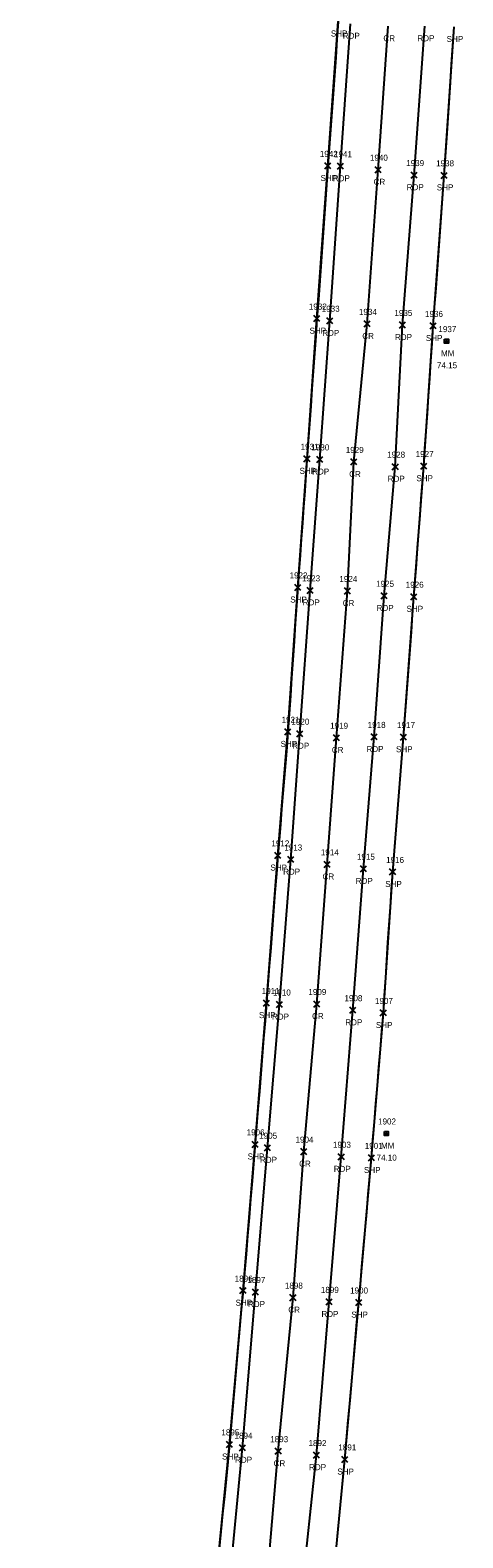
# Model space of a CAD drawing. Extents: x 1688195 to 1692013, y 424605 to 441234.
# Drawn here: x 1690497 to 1690640, y 435648 to 436148 of the extents above; entities that cross this region are included whole.
import ezdxf

# ---------------------------------------------------------------- set-up
doc = ezdxf.new("R2010")
doc.units = 0
for name, color, linetype in [('LSOGP', 7, 'Continuous'), ('P_A', 7, 'Continuous'), ('P_I', 7, 'Continuous'), ('P_TIC', 7, 'Continuous'), ('PET', 7, 'Continuous'), ('PRC', 7, 'Continuous'), ('PSP', 7, 'Continuous'), ('S_A', 7, 'Continuous'), ('S_C', 7, 'Continuous'), ('S_I', 7, 'Continuous'), ('SRM', 7, 'Continuous')]:
    doc.layers.add(name, color=color, linetype=linetype)

msp = doc.modelspace()

# ---------------------------------------------------------------- linework, layer by layer
at = {"layer": 'LSOGP'}
for points in [[(1690599.5, 436156.87), (1690598.67, 436145.19), (1690598.25, 436139.19), (1690597.82, 436133.2), (1690597.39, 436127.2), (1690596.96, 436121.21), (1690596.53, 436115.22), (1690596.11, 436109.22), (1690595.68, 436103.23), (1690595.22, 436096.9), (1690594.77, 436090.56), (1690594.31, 436084.23), (1690593.85, 436077.89), (1690593.4, 436071.56), (1690592.94, 436065.22), (1690592.49, 436058.89), (1690592.03, 436052.55), (1690591.62, 436046.74), (1690591.2, 436040.93), (1690590.79, 436035.11), (1690590.38, 436029.3), (1690589.97, 436023.48), (1690589.56, 436017.67), (1690589.14, 436011.86), (1690588.35, 436000.7), (1690587.96, 435995.36), (1690587.57, 435990.02), (1690587.19, 435984.68), (1690586.8, 435979.34), (1690586.41, 435974.01), (1690586.03, 435968.67), (1690585.64, 435963.33), (1690585.24, 435957.34), (1690584.84, 435951.35), (1690584.43, 435945.36), (1690584.03, 435939.37), (1690583.63, 435933.39), (1690583.23, 435927.4), (1690582.82, 435921.41), (1690582.42, 435915.42), (1690582, 435910.29), (1690581.58, 435905.17), (1690581.16, 435900.04), (1690580.74, 435894.91), (1690580.32, 435889.78), (1690579.9, 435884.65), (1690579.48, 435879.52), (1690579.05, 435874.39), (1690578.58, 435868.27), (1690578.11, 435862.15), (1690577.64, 435856.03), (1690577.17, 435849.91), (1690576.69, 435843.79), (1690576.22, 435837.66), (1690575.75, 435831.54), (1690575.28, 435825.42), (1690574.81, 435819.56), (1690574.34, 435813.69), (1690573.88, 435807.83), (1690573.41, 435801.97), (1690572.94, 435796.1), (1690572.47, 435790.24), (1690570.53, 435766.38), (1690570.03, 435760.31), (1690569.52, 435754.25), (1690569.02, 435748.18), (1690568.52, 435742.11), (1690568.01, 435736.05), (1690567.51, 435729.98), (1690566.95, 435723.6), (1690566.39, 435717.22), (1690565.84, 435710.84), (1690565.28, 435704.46), (1690564.72, 435698.08), (1690564.16, 435691.7), (1690563.6, 435685.31), (1690563.05, 435678.93), (1690562.47, 435673.17), (1690561.9, 435667.4), (1690561.33, 435661.63), (1690560.76, 435655.87), (1690560.18, 435650.1), (1690559.61, 435644.34)], [(1690598.48, 435644.97), (1690599.03, 435650.77), (1690599.59, 435656.56), (1690600.14, 435662.36), (1690600.7, 435668.15), (1690601.25, 435673.95), (1690601.83, 435680.46), (1690602.41, 435686.97), (1690602.99, 435693.48), (1690603.57, 435699.99), (1690604.15, 435706.5), (1690604.72, 435713.01), (1690605.3, 435719.52), (1690605.88, 435726.03), (1690606.41, 435732.03), (1690606.93, 435738.03), (1690607.46, 435744.03), (1690607.98, 435750.02), (1690608.51, 435756.02), (1690609.03, 435762.02), (1690609.56, 435768.02), (1690610.09, 435774.02), (1690610.58, 435780.03), (1690611.07, 435786.04), (1690611.57, 435792.06), (1690612.06, 435798.07), (1690612.55, 435804.09), (1690613.05, 435810.1), (1690613.54, 435816.12), (1690614.04, 435822.13), (1690614.42, 435827.98), (1690614.81, 435833.83), (1690615.2, 435839.68), (1690615.58, 435845.52), (1690615.97, 435851.37), (1690616.36, 435857.22), (1690616.74, 435863.07), (1690617.58, 435874.51), (1690618.02, 435880.1), (1690618.47, 435885.69), (1690618.92, 435891.28), (1690619.37, 435896.87), (1690619.81, 435902.46), (1690620.26, 435908.05), (1690620.71, 435913.65), (1690621.14, 435919.47), (1690621.58, 435925.3), (1690622.02, 435931.12), (1690622.45, 435936.95), (1690622.89, 435942.78), (1690623.32, 435948.6), (1690623.76, 435954.43), (1690624.19, 435960.25), (1690624.6, 435965.67), (1690625.01, 435971.09), (1690625.41, 435976.51), (1690625.82, 435981.93), (1690626.23, 435987.35), (1690626.63, 435992.77), (1690627.04, 435998.19), (1690627.45, 436003.61), (1690627.84, 436009.42), (1690628.23, 436015.24), (1690628.63, 436021.05), (1690629.02, 436026.86), (1690629.42, 436032.68), (1690629.81, 436038.49), (1690630.21, 436044.31), (1690630.6, 436050.12), (1690631.05, 436056.37), (1690631.51, 436062.62), (1690631.96, 436068.86), (1690632.41, 436075.11), (1690632.87, 436081.36), (1690633.32, 436087.61), (1690633.77, 436093.86), (1690634.23, 436100.1), (1690634.63, 436106.26), (1690635.04, 436112.42), (1690636.27, 436130.89), (1690636.68, 436137.05), (1690637.08, 436143.21), (1690637.49, 436149.36)]]:
    msp.add_lwpolyline(points, dxfattribs=at)
at = {"layer": 'P_TIC'}
for points in [[(1690594.68, 436102.23), (1690596.68, 436104.23)], [(1690596.68, 436102.23), (1690594.68, 436104.23)], [(1690598.8, 436102.13), (1690600.8, 436104.13)], [(1690600.8, 436102.13), (1690598.8, 436104.13)], [(1690611.37, 436100.96), (1690613.37, 436102.96)], [(1690613.37, 436100.96), (1690611.37, 436102.96)], [(1690623.3, 436099.17), (1690625.3, 436101.17)], [(1690625.3, 436099.17), (1690623.3, 436101.17)], [(1690633.23, 436099.1), (1690635.23, 436101.1)], [(1690635.23, 436099.1), (1690633.23, 436101.1)], [(1690591.03, 436051.55), (1690593.03, 436053.55)], [(1690593.03, 436051.55), (1690591.03, 436053.55)], [(1690595.29, 436050.83), (1690597.29, 436052.83)], [(1690597.29, 436050.83), (1690595.29, 436052.83)], [(1690607.63, 436049.8), (1690609.63, 436051.8)], [(1690609.63, 436049.8), (1690607.63, 436051.8)], [(1690619.4, 436049.44), (1690621.4, 436051.44)], [(1690621.4, 436049.44), (1690619.4, 436051.44)], [(1690629.6, 436049.12), (1690631.6, 436051.12)], [(1690631.6, 436049.12), (1690629.6, 436051.12)], [(1690587.73, 436005.04), (1690589.73, 436007.04)], [(1690589.73, 436005.04), (1690587.73, 436007.04)], [(1690591.94, 436004.81), (1690593.94, 436006.81)], [(1690593.94, 436004.81), (1690591.94, 436006.81)], [(1690603.28, 436003.98), (1690605.28, 436005.98)], [(1690605.28, 436003.98), (1690603.28, 436005.98)], [(1690617.01, 436002.42), (1690619.01, 436004.42)], [(1690619.01, 436002.42), (1690617.01, 436004.42)], [(1690626.45, 436002.61), (1690628.45, 436004.61)], [(1690628.45, 436002.61), (1690626.45, 436004.61)], [(1690584.64, 435962.33), (1690586.64, 435964.33)], [(1690586.64, 435962.33), (1690584.64, 435964.33)], [(1690588.82, 435961.37), (1690590.82, 435963.37)], [(1690590.82, 435961.37), (1690588.82, 435963.37)], [(1690601.14, 435961.16), (1690603.14, 435963.16)], [(1690603.14, 435961.16), (1690601.14, 435963.16)], [(1690613.33, 435959.55), (1690615.33, 435961.55)], [(1690615.33, 435959.55), (1690613.33, 435961.55)], [(1690623.19, 435959.25), (1690625.19, 435961.25)], [(1690625.19, 435959.25), (1690623.19, 435961.25)], [(1690581.42, 435914.42), (1690583.42, 435916.42)], [(1690583.42, 435914.42), (1690581.42, 435916.42)], [(1690585.33, 435913.81), (1690587.33, 435915.81)], [(1690587.33, 435913.81), (1690585.33, 435915.81)], [(1690597.53, 435912.43), (1690599.53, 435914.43)], [(1690599.53, 435912.43), (1690597.53, 435914.43)], [(1690609.97, 435912.73), (1690611.97, 435914.73)], [(1690611.97, 435912.73), (1690609.97, 435914.73)], [(1690619.71, 435912.65), (1690621.71, 435914.65)], [(1690621.71, 435912.65), (1690619.71, 435914.65)], [(1690578.05, 435873.39), (1690580.05, 435875.39)], [(1690580.05, 435873.39), (1690578.05, 435875.39)], [(1690582.32, 435872.03), (1690584.32, 435874.03)], [(1690584.32, 435872.03), (1690582.32, 435874.03)], [(1690594.45, 435870.42), (1690596.45, 435872.42)], [(1690596.45, 435870.42), (1690594.45, 435872.42)], [(1690606.41, 435868.96), (1690608.41, 435870.96)], [(1690608.41, 435868.96), (1690606.41, 435870.96)], [(1690616.13, 435867.92), (1690618.13, 435869.92)], [(1690618.13, 435867.92), (1690616.13, 435869.92)], [(1690574.28, 435824.42), (1690576.28, 435826.42)], [(1690576.28, 435824.42), (1690574.28, 435826.42)], [(1690578.63, 435823.92), (1690580.63, 435825.92)], [(1690580.63, 435823.92), (1690578.63, 435825.92)], [(1690590.96, 435824.1), (1690592.96, 435826.1)], [(1690592.96, 435824.1), (1690590.96, 435826.1)], [(1690602.92, 435822.04), (1690604.92, 435824.04)], [(1690604.92, 435822.04), (1690602.92, 435824.04)], [(1690613.04, 435821.13), (1690615.04, 435823.13)], [(1690615.04, 435821.13), (1690613.04, 435823.13)], [(1690570.54, 435777.51), (1690572.54, 435779.51)], [(1690572.54, 435777.51), (1690570.54, 435779.51)], [(1690574.66, 435776.41), (1690576.66, 435778.41)], [(1690576.66, 435776.41), (1690574.66, 435778.41)], [(1690586.69, 435775.1), (1690588.69, 435777.1)], [(1690588.69, 435775.1), (1690586.69, 435777.1)], [(1690599.11, 435773.4), (1690601.11, 435775.4)], [(1690601.11, 435773.4), (1690599.11, 435775.4)], [(1690609.09, 435773.02), (1690611.09, 435775.02)], [(1690611.09, 435773.02), (1690609.09, 435775.02)], [(1690566.51, 435728.98), (1690568.51, 435730.98)], [(1690568.51, 435728.98), (1690566.51, 435730.98)], [(1690570.67, 435728.52), (1690572.67, 435730.52)], [(1690572.67, 435728.52), (1690570.67, 435730.52)], [(1690583.09, 435726.65), (1690585.09, 435728.65)], [(1690585.09, 435726.65), (1690583.09, 435728.65)], [(1690595.03, 435725.24), (1690597.03, 435727.24)], [(1690597.03, 435725.24), (1690595.03, 435727.24)], [(1690604.88, 435725.03), (1690606.88, 435727.03)], [(1690606.88, 435725.03), (1690604.88, 435727.03)], [(1690562.05, 435677.93), (1690564.05, 435679.93)], [(1690564.05, 435677.93), (1690562.05, 435679.93)], [(1690566.39, 435676.85), (1690568.39, 435678.85)], [(1690568.39, 435676.85), (1690566.39, 435678.85)], [(1690578.22, 435675.69), (1690580.22, 435677.69)], [(1690580.22, 435675.69), (1690578.22, 435677.69)], [(1690590.92, 435674.4), (1690592.92, 435676.4)], [(1690592.92, 435674.4), (1690590.92, 435676.4)], [(1690600.25, 435672.95), (1690602.25, 435674.95)], [(1690602.25, 435672.95), (1690600.25, 435674.95)]]:
    msp.add_lwpolyline(points, dxfattribs=at)
at = {"layer": 'PET'}
for points in [[(1690501.19, 435117.33), (1690507.41, 435161.22), (1690513.67, 435205.88), (1690519.63, 435254.45), (1690525.65, 435299.76), (1690531.81, 435349.11), (1690537.74, 435397.15), (1690543.58, 435444.91), (1690548.36, 435492.43), (1690553.28, 435538.48), (1690558.17, 435585.77), (1690562.99, 435632.63), (1690567.39, 435677.85), (1690571.67, 435729.52), (1690575.66, 435777.41), (1690579.63, 435824.92), (1690583.32, 435873.03), (1690586.33, 435914.81), (1690589.82, 435962.37), (1690592.94, 436005.81), (1690596.29, 436051.83), (1690599.8, 436103.13), (1690603.11, 436150.42)], [(1690525.5, 435112.81), (1690531.76, 435157.71), (1690537.76, 435203.09), (1690544.15, 435250.79), (1690550.01, 435296.11), (1690556.39, 435345.44), (1690562.09, 435393.57), (1690567.56, 435441.2), (1690572.36, 435489.16), (1690577.37, 435534.18), (1690582.68, 435583.71), (1690586.85, 435628.48), (1690591.92, 435675.4), (1690596.03, 435726.24), (1690600.11, 435774.4), (1690603.92, 435823.04), (1690607.41, 435869.96), (1690610.97, 435913.73), (1690614.33, 435960.55), (1690618.01, 436003.42), (1690620.4, 436050.44), (1690624.3, 436100.17), (1690627.83, 436149.61)]]:
    msp.add_lwpolyline(points, dxfattribs=at)
at = {"layer": 'PRC'}
msp.add_lwpolyline([(1690513.41, 435116), (1690519.53, 435159.11), (1690525.48, 435205.46), (1690532.12, 435252.74), (1690538.16, 435298.47), (1690544.06, 435346.3), (1690550.13, 435396.05), (1690555.89, 435442.49), (1690560.85, 435491.32), (1690565.49, 435535.56), (1690570.86, 435584.47), (1690575.18, 435630.07), (1690579.22, 435676.69), (1690584.09, 435727.65), (1690587.69, 435776.1), (1690591.96, 435825.1), (1690595.45, 435871.42), (1690598.53, 435913.43), (1690602.14, 435962.16), (1690604.28, 436004.98), (1690608.63, 436050.8), (1690612.37, 436101.96), (1690615.61, 436149.6)], dxfattribs=at)
at = {"layer": 'PSP'}
for points in [[(1690496.95, 435118.58), (1690503.25, 435162.44), (1690509.51, 435207.35), (1690515.85, 435255.4), (1690521.64, 435301.74), (1690527.7, 435348.89), (1690533.61, 435398.55), (1690540.53, 435445.33), (1690544.23, 435493.64), (1690548.91, 435538.68), (1690553.85, 435586.59), (1690558.47, 435632.8), (1690563.05, 435678.93), (1690567.51, 435729.98), (1690571.54, 435778.51), (1690575.28, 435825.42), (1690579.05, 435874.39), (1690582.42, 435915.42), (1690585.64, 435963.33), (1690588.73, 436006.04), (1690592.03, 436052.55), (1690595.68, 436103.23), (1690599.1, 436151.18)], [(1690535.08, 435111.69), (1690541.36, 435156.27), (1690547.71, 435202), (1690554, 435247.6), (1690559.59, 435294.31), (1690565.75, 435344.26), (1690571.6, 435392), (1690577.62, 435439.9), (1690582.42, 435487.22), (1690587.27, 435533.5), (1690591.92, 435582.16), (1690596.81, 435627.59), (1690601.25, 435673.95), (1690605.88, 435726.03), (1690610.09, 435774.02), (1690614.04, 435822.13), (1690617.13, 435868.92), (1690620.71, 435913.65), (1690624.19, 435960.25), (1690627.45, 436003.61), (1690630.6, 436050.12), (1690634.23, 436100.1), (1690637.49, 436149.36)]]:
    msp.add_lwpolyline(points, dxfattribs=at)
at = {"layer": 'SRM'}
for points in [[(1690634.35, 436045.7), (1690635.6, 436045.7), (1690635.6, 436044.45), (1690634.35, 436044.45)], [(1690614.44, 435782.74), (1690615.69, 435782.74), (1690615.69, 435781.49), (1690614.44, 435781.49)]]:
    msp.add_lwpolyline(points, close=True, dxfattribs=at)
for centre in [(1690634.98, 436045.07), (1690615.06, 435782.12)]:
    msp.add_circle(centre, 0.0833, dxfattribs=at)

# ---------------------------------------------------------------- texts
at = {"layer": 'P_A'}
for s, p in [('SHP', (1690596.64, 436146.18)), ('RDP', (1690600.59, 436145.42)), ('CR', (1690614.04, 436144.6)), ('RDP', (1690625.32, 436144.61)), ('SHP', (1690635.03, 436144.36)), ('SHP', (1690593.21, 436098.23)), ('RDP', (1690597.29, 436098.13)), ('CR', (1690610.81, 436096.96)), ('RDP', (1690621.79, 436095.17)), ('SHP', (1690631.76, 436095.1)), ('SHP', (1690589.56, 436047.55)), ('RDP', (1690593.78, 436046.83)), ('CR', (1690607.06, 436045.8)), ('RDP', (1690617.89, 436045.44)), ('SHP', (1690628.14, 436045.12)), ('SHP', (1690586.27, 436001.04)), ('RDP', (1690590.43, 436000.81)), ('CR', (1690602.71, 435999.98)), ('RDP', (1690615.49, 435998.42)), ('SHP', (1690624.98, 435998.61)), ('SHP', (1690583.18, 435958.33)), ('RDP', (1690587.31, 435957.37)), ('CR', (1690600.57, 435957.16)), ('RDP', (1690611.81, 435955.55)), ('SHP', (1690621.73, 435955.25)), ('SHP', (1690579.96, 435910.42)), ('RDP', (1690583.82, 435909.81)), ('CR', (1690596.96, 435908.43)), ('RDP', (1690608.46, 435908.73)), ('SHP', (1690618.24, 435908.65)), ('SHP', (1690576.59, 435869.39)), ('RDP', (1690580.8, 435868.03)), ('CR', (1690593.88, 435866.42)), ('RDP', (1690604.89, 435864.96)), ('SHP', (1690614.66, 435863.92)), ('SHP', (1690572.81, 435820.42)), ('RDP', (1690577.12, 435819.92)), ('CR', (1690590.4, 435820.1)), ('RDP', (1690601.41, 435818.04)), ('SHP', (1690611.57, 435817.13)), ('SHP', (1690569.07, 435773.51)), ('RDP', (1690573.14, 435772.41)), ('CR', (1690586.13, 435771.1)), ('RDP', (1690597.6, 435769.4)), ('SHP', (1690607.62, 435769.02)), ('SHP', (1690565.05, 435724.98)), ('RDP', (1690569.16, 435724.52)), ('CR', (1690582.52, 435722.65)), ('RDP', (1690593.51, 435721.24)), ('SHP', (1690603.42, 435721.03)), ('SHP', (1690560.58, 435673.93)), ('RDP', (1690564.88, 435672.85)), ('CR', (1690577.66, 435671.69)), ('RDP', (1690589.41, 435670.4)), ('SHP', (1690598.79, 435668.95))]:
    msp.add_text(s, height=2, dxfattribs=at).set_placement(p)
at = {"layer": 'P_I'}
for s, p in [('1942', (1690592.98, 436106.23)), ('1941', (1690597.68, 436106.13)), ('1940', (1690609.59, 436104.96)), ('1939', (1690621.6, 436103.17)), ('1938', (1690631.53, 436103.1)), ('1932', (1690589.34, 436055.55)), ('1933', (1690593.6, 436054.83)), ('1934', (1690605.94, 436053.8)), ('1935', (1690617.71, 436053.44)), ('1936', (1690627.85, 436053.12)), ('1931', (1690586.61, 436009.04)), ('1930', (1690590.17, 436008.81)), ('1929', (1690601.58, 436007.98)), ('1928', (1690615.31, 436006.42)), ('1927', (1690624.75, 436006.61)), ('1922', (1690582.95, 435966.33)), ('1923', (1690587.13, 435965.37)), ('1924', (1690599.45, 435965.16)), ('1925', (1690611.63, 435963.55)), ('1926', (1690621.45, 435963.25)), ('1921', (1690580.3, 435918.42)), ('1920', (1690583.55, 435917.81)), ('1919', (1690596.39, 435916.43)), ('1918', (1690608.84, 435916.73)), ('1917', (1690618.58, 435916.65)), ('1912', (1690576.93, 435877.39)), ('1913', (1690581.19, 435876.03)), ('1914', (1690593.32, 435874.42)), ('1915', (1690605.28, 435872.96)), ('1916', (1690614.95, 435871.92)), ('1911', (1690573.72, 435828.42)), ('1910', (1690577.42, 435827.92)), ('1909', (1690589.19, 435828.1)), ('1908', (1690601.15, 435826.04)), ('1907', (1690611.26, 435825.13)), ('1906', (1690568.71, 435781.51)), ('1905', (1690572.88, 435780.41)), ('1904', (1690584.92, 435779.1)), ('1903', (1690597.34, 435777.4)), ('1901', (1690607.88, 435777.02)), ('1896', (1690564.76, 435732.98)), ('1897', (1690568.98, 435732.52)), ('1898', (1690581.4, 435730.65)), ('1899', (1690593.33, 435729.24)), ('1900', (1690603.02, 435729.03)), ('1895', (1690560.35, 435681.93)), ('1894', (1690564.7, 435680.85)), ('1893', (1690576.53, 435679.69)), ('1892', (1690589.23, 435678.4)), ('1891', (1690599.12, 435676.95))]:
    msp.add_text(s, height=2, dxfattribs=at).set_placement(p)
at = {"layer": 'S_A'}
for p in [(1690633.17, 436040.07), (1690613.25, 435777.12)]:
    msp.add_text('MM', height=2, dxfattribs=at).set_placement(p)
at = {"layer": 'S_C'}
for s, p in [('74.15', (1690631.8, 436036.07)), ('74.10', (1690611.79, 435773.12))]:
    msp.add_text(s, height=2, dxfattribs=at).set_placement(p)
at = {"layer": 'S_I'}
for s, p in [('1937', (1690632.29, 436048.07)), ('1902', (1690612.29, 435785.12))]:
    msp.add_text(s, height=2, dxfattribs=at).set_placement(p)

doc.saveas('drawing.dxf')
